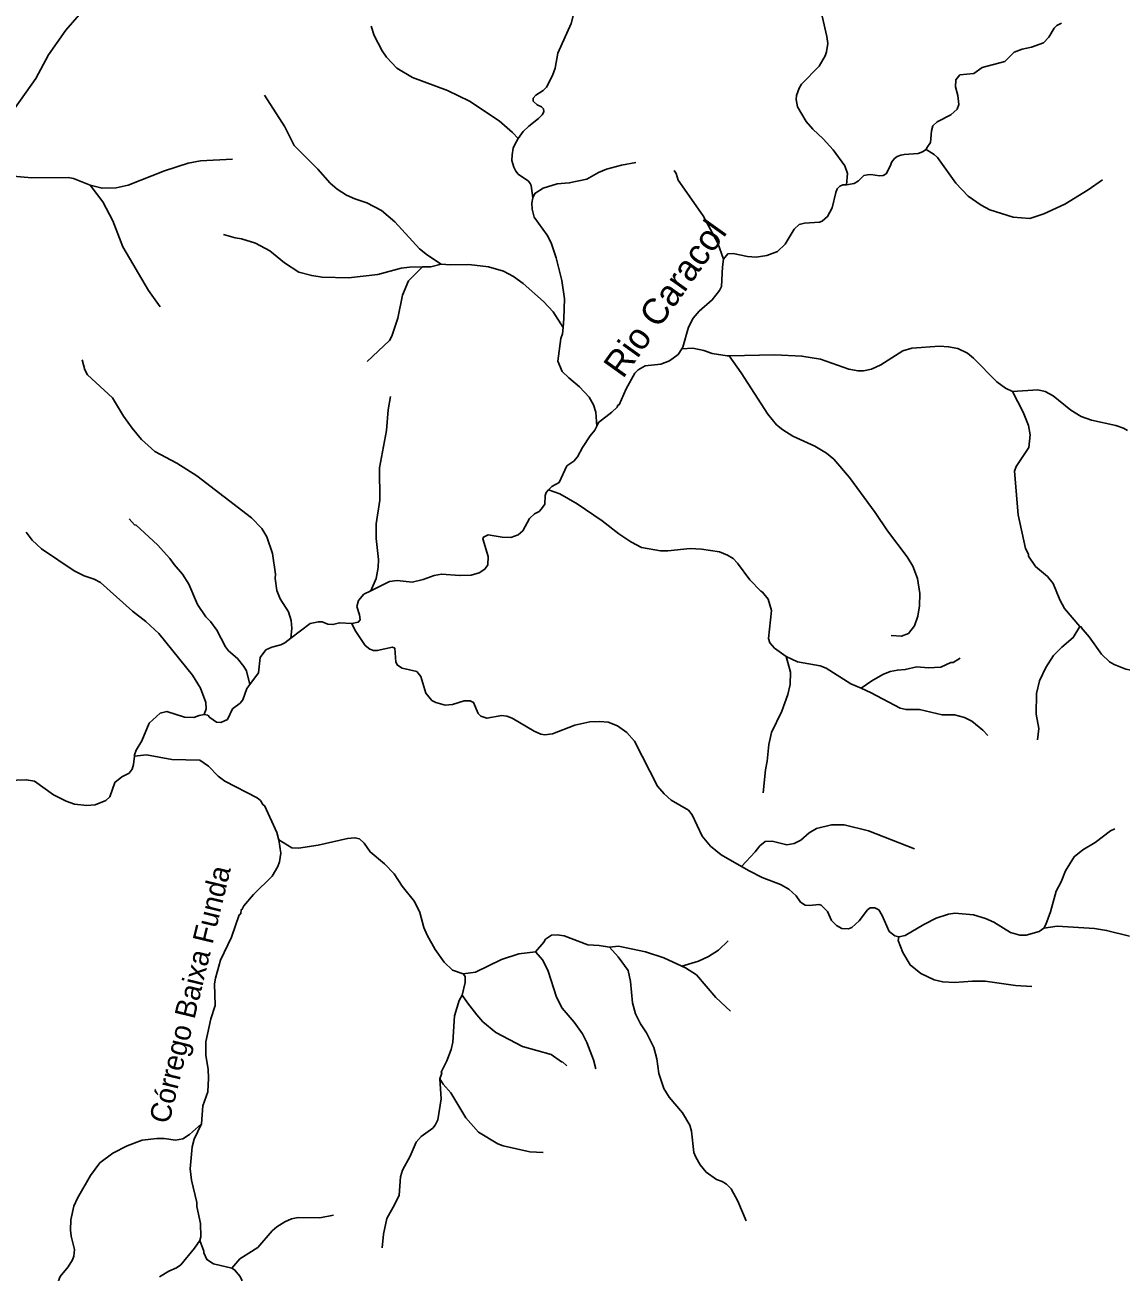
# Model space of a CAD drawing. Extents: x 280.4 to 335.6, y 8893.9 to 8949.5.
# Drawn here: x 321.4 to 329.87, y 8900.11 to 8909.74 of the extents above; entities that cross this region are included whole.
import ezdxf
from ezdxf.enums import TextEntityAlignment as Align

# ---------------------------------------------------------------- set-up
doc = ezdxf.new("R2010")
doc.units = 0
doc.header["$LTSCALE"] = 0.064
doc.layers.add('61', color=7, linetype='Continuous')
doc.layers.add('7', color=7, linetype='Continuous', lineweight=25)

msp = doc.modelspace()

# ---------------------------------------------------------------- linework, layer by layer
at = {"layer": '7'}
for points in [[(325.6886, 8910.0258), (325.6906, 8910.0157), (325.623, 8909.7531), (325.5192, 8909.5228), (325.4982, 8909.4077), (325.479, 8909.3501), (325.4308, 8909.2615), (325.4059, 8909.2345), (325.3501, 8909.1984), (325.3291, 8909.1772), (325.3294, 8909.1518), (325.3605, 8909.1249), (325.3924, 8909.1084), (325.4093, 8909.0931), (325.4101, 8909.0711), (325.3994, 8909.0462), (325.3707, 8909.0181), (325.2946, 8908.9593), (325.2526, 8908.9187), (325.2118, 8908.8645)], [(321.8219, 8909.8184), (321.7176, 8909.7002), (321.5856, 8909.5113), (321.4877, 8909.3291), (321.3251, 8909.0992), (321.3092, 8909.0653), (321.2855, 8908.9827), (321.2779, 8908.9278), (321.2778, 8908.7808), (321.2699, 8908.7207), (321.241, 8908.6561), (321.1893, 8908.5767)], [(327.5613, 8909.8081), (327.5978, 8909.6523), (327.6041, 8909.5974), (327.5963, 8909.5349), (327.5855, 8909.5042), (327.5373, 8909.4221), (327.4015, 8909.2829), (327.3839, 8909.2541), (327.3632, 8909.1965), (327.3615, 8909.167), (327.3714, 8909.1096), (327.4372, 8908.9964), (327.4897, 8908.9356), (327.5705, 8908.8611), (327.6476, 8908.7776), (327.7356, 8908.6528), (327.7564, 8908.5945), (327.7507, 8908.5076)], [(329.4108, 8909.7542), (329.3742, 8909.7378), (329.3533, 8909.7157), (329.3136, 8909.647), (329.2714, 8909.6033), (329.1788, 8909.5694), (329.1071, 8909.5546), (329.0454, 8909.5315), (328.9726, 8909.458), (328.7972, 8909.4141)], [(324.0776, 8909.7331), (324.1012, 8909.6593), (324.1614, 8909.5421), (324.197, 8909.4919), (324.2765, 8909.4077), (324.3977, 8909.3352), (324.6668, 8909.2358), (324.8361, 8909.1516), (325.0659, 8909.0001), (325.1696, 8908.9114), (325.2118, 8908.8645)], [(328.7972, 8909.4141), (328.7328, 8909.3662), (328.6252, 8909.3552), (328.5941, 8909.3187), (328.5929, 8909.2645), (328.6105, 8909.1958), (328.6166, 8909.1279), (328.6057, 8909.0918), (328.555, 8909.0467), (328.4505, 8908.9927), (328.4178, 8908.9623), (328.4073, 8908.9239), (328.3974, 8908.8335), (328.3703, 8908.7914), (328.3657, 8908.7804)], [(323.2542, 8909.2004), (323.4104, 8908.9547), (323.4819, 8908.8093), (323.6659, 8908.6284), (323.7609, 8908.519), (323.8144, 8908.4732), (323.8879, 8908.4282), (323.9519, 8908.3986), (324.0445, 8908.3669), (324.1574, 8908.3092), (324.2614, 8908.2217), (324.451, 8908.0128), (324.513, 8907.9626), (324.6186, 8907.8951)], [(325.2118, 8908.8645), (325.1849, 8908.8129), (325.1737, 8908.791), (325.1661, 8908.7378), (325.1644, 8908.6935), (325.1804, 8908.6426), (325.1954, 8908.6124), (325.2142, 8908.5902), (325.2925, 8908.535), (325.3056, 8908.5162), (325.314, 8908.5021), (325.327, 8908.407)], [(323.0068, 8908.7049), (322.7594, 8908.6913), (322.6629, 8908.6752), (322.4799, 8908.6148), (322.1995, 8908.5037), (322.1067, 8908.4833), (321.9983, 8908.4807), (321.9075, 8908.503)], [(328.3657, 8908.7804), (328.3376, 8908.7606), (328.3045, 8908.7481), (328.1962, 8908.7407), (328.1689, 8908.7358), (328.1413, 8908.7259), (328.1194, 8908.7095), (328.0993, 8908.6832), (328.0872, 8908.6514), (328.0557, 8908.5928), (328.032, 8908.5797), (328.0036, 8908.5762), (327.9383, 8908.5857), (327.9126, 8908.585), (327.8841, 8908.5779), (327.8643, 8908.5604), (327.8429, 8908.5383), (327.8098, 8908.5174), (327.7507, 8908.5076)], [(329.7281, 8908.546), (329.6176, 8908.4681), (329.4351, 8908.3574), (329.2747, 8908.2836), (329.1663, 8908.2467), (329.0375, 8908.2568), (328.8568, 8908.3138), (328.789, 8908.3493), (328.6884, 8908.4197), (328.5934, 8908.5194), (328.4521, 8908.7167), (328.4257, 8908.7411), (328.3657, 8908.7804)], [(326.1213, 8908.6782), (326.0105, 8908.6581), (325.8959, 8908.6285), (325.8325, 8908.6016), (325.7439, 8908.5503), (325.6081, 8908.5217), (325.5132, 8908.5152), (325.4065, 8908.4806), (325.3423, 8908.4403), (325.327, 8908.407)], [(326.4171, 8908.6176), (326.4335, 8908.5948), (326.4503, 8908.5435), (326.6424, 8908.2672), (326.755, 8908.0554), (326.8003, 8907.9338)], [(321.9075, 8908.503), (321.7777, 8908.5563), (321.7377, 8908.5632), (321.4569, 8908.5601), (321.281, 8908.576), (321.1893, 8908.5767)], [(322.4461, 8907.5652), (322.3561, 8907.6906), (322.1579, 8908.0285), (322.0809, 8908.2299), (322.0055, 8908.3745), (321.9075, 8908.503)], [(327.7507, 8908.5076), (327.7216, 8908.5067), (327.6984, 8908.4959), (327.6767, 8908.4758), (327.6665, 8908.4485), (327.6401, 8908.3281), (327.6039, 8908.2622), (327.5621, 8908.2273), (327.5412, 8908.2197), (327.4261, 8908.2098), (327.3843, 8908.1992), (327.3462, 8908.1637), (327.2766, 8908.0484), (327.216, 8907.9932), (327.1336, 8907.9602), (327.0523, 8907.9477), (326.986, 8907.953), (326.8745, 8907.9763), (326.8324, 8907.9734), (326.8003, 8907.9338)], [(325.327, 8908.407), (325.3178, 8908.3643), (325.3208, 8908.3197), (325.3362, 8908.2564), (325.4359, 8908.1179), (325.4678, 8908.0579), (325.506, 8907.9434), (325.5514, 8907.7684), (325.5702, 8907.6261), (325.567, 8907.4757), (325.5595, 8907.4055)], [(322.9365, 8908.1242), (323.0256, 8908.0969), (323.0759, 8908.0904), (323.1841, 8908.0562), (323.2955, 8907.9959), (323.4083, 8907.9037), (323.5194, 8907.8336), (323.6181, 8907.8056), (323.6986, 8907.7929), (323.9031, 8907.7893), (324.1284, 8907.815), (324.3093, 8907.8631), (324.3726, 8907.8706), (324.4728, 8907.873)], [(326.8003, 8907.9338), (326.7921, 8907.8723), (326.7837, 8907.7214), (326.7696, 8907.6901), (326.7121, 8907.6181), (326.6119, 8907.5306), (326.5646, 8907.4766), (326.5283, 8907.4086), (326.4853, 8907.2544), (326.4766, 8907.2408)], [(324.0474, 8907.1415), (324.2179, 8907.3043), (324.2372, 8907.3369), (324.2846, 8907.4764), (324.3199, 8907.6555), (324.3659, 8907.7661), (324.4728, 8907.873)], [(324.4728, 8907.873), (324.5382, 8907.8746), (324.6186, 8907.8951)], [(324.6186, 8907.8951), (324.69, 8907.8885), (324.8331, 8907.8914), (324.9832, 8907.8742), (325.0993, 8907.839), (325.1762, 8907.7992), (325.2522, 8907.744), (325.4093, 8907.6064), (325.4843, 8907.5263), (325.5595, 8907.4055)], [(325.5595, 8907.4055), (325.5543, 8907.3568), (325.5416, 8907.3197), (325.5194, 8907.1451)], [(326.8429, 8907.1859), (326.8265, 8907.1855), (326.7112, 8907.2036), (326.6481, 8907.2262), (326.5633, 8907.2451), (326.4766, 8907.2408)], [(329.0309, 8906.911), (328.9785, 8906.9368), (328.91, 8906.9855), (328.7318, 8907.1673), (328.6833, 8907.2074), (328.6088, 8907.2422), (328.5384, 8907.2566), (328.4674, 8907.2614), (328.254, 8907.2449), (328.1851, 8907.2254), (328.0139, 8907.116), (327.9435, 8907.084), (327.8808, 8907.0705), (327.8388, 8907.0696), (327.7669, 8907.0842), (327.5476, 8907.1605), (327.4055, 8907.1847), (327.1959, 8907.1942), (326.8429, 8907.1859)], [(321.8446, 8907.1551), (321.866, 8907.0786), (321.8847, 8907.0402), (322.078, 8906.8628), (322.1651, 8906.7216), (322.2319, 8906.6268), (322.3035, 8906.5412), (322.4065, 8906.4468), (322.577, 8906.3566), (322.7315, 8906.2587), (323.1526, 8905.9349), (323.2316, 8905.8527), (323.2718, 8905.7876), (323.3152, 8905.659), (323.3375, 8905.4998), (323.3346, 8905.4663), (323.3475, 8905.3736), (323.3732, 8905.3097), (323.4376, 8905.2096), (323.4593, 8905.1433), (323.4656, 8905.08), (323.4567, 8905.0053)], [(326.4766, 8907.2408), (326.4487, 8907.1971), (326.3815, 8907.1467), (326.3148, 8907.1207), (326.193, 8907.1096), (326.1411, 8907.0785), (326.1144, 8907.0535), (326.0467, 8906.9318), (325.9926, 8906.8068), (325.9828, 8906.8048), (325.9774, 8906.7909), (325.9374, 8906.7508), (325.8348, 8906.6726), (325.8209, 8906.6432)], [(328.0943, 8905.0261), (328.1747, 8905.0223), (328.2282, 8905.0419), (328.2758, 8905.1018), (328.301, 8905.177), (328.3145, 8905.2566), (328.3161, 8905.3512), (328.297, 8905.4664), (328.2615, 8905.5621), (328.2174, 8905.6343), (328.0667, 8905.835), (327.9723, 8905.9773), (327.7736, 8906.2465), (327.6513, 8906.3877), (327.5951, 8906.435), (327.5051, 8906.4884), (327.3349, 8906.5654), (327.257, 8906.6151), (327.2089, 8906.6544), (327.1408, 8906.737), (326.9348, 8907.0561), (326.8429, 8907.1859)], [(325.5194, 8907.1451), (325.5525, 8907.0662), (325.6035, 8907.0156), (325.6869, 8906.948), (325.7614, 8906.8666), (325.7938, 8906.8079), (325.8128, 8906.7513), (325.8209, 8906.6432)], [(324.2279, 8906.8725), (324.209, 8906.7699), (324.196, 8906.61), (324.1406, 8906.3218), (324.1437, 8906.0716), (324.1149, 8905.8891), (324.1165, 8905.7749), (324.1341, 8905.6142), (324.1308, 8905.5519), (324.1167, 8905.4677), (324.0736, 8905.3718)], [(329.9197, 8906.6108), (329.8897, 8906.6281), (329.8306, 8906.649), (329.6414, 8906.6906), (329.5613, 8906.7182), (329.4821, 8906.7657), (329.3467, 8906.8772), (329.2853, 8906.9111), (329.2286, 8906.9224), (329.0309, 8906.911)], [(329.5529, 8905.0957), (329.433, 8905.2362), (329.3982, 8905.3023), (329.3472, 8905.4293), (329.3028, 8905.4814), (329.2086, 8905.5599), (329.1563, 8905.6392), (329.1549, 8905.6543), (329.1335, 8905.699), (329.0759, 8905.9596), (329.0473, 8906.2954), (329.0599, 8906.3307), (329.1591, 8906.4795), (329.1685, 8906.5762), (329.1554, 8906.648), (329.1134, 8906.7513), (329.0309, 8906.911)], [(325.8209, 8906.6432), (325.8059, 8906.6113), (325.7682, 8906.5686), (325.7094, 8906.4794), (325.6705, 8906.4069), (325.643, 8906.3737), (325.5892, 8906.3363), (325.5308, 8906.2087), (325.4724, 8906.1777), (325.4472, 8906.1504)], [(325.4472, 8906.1504), (325.4302, 8906.132), (325.4218, 8906.1084), (325.4185, 8906.0411), (325.3944, 8906.0037), (325.3745, 8905.9852), (325.3387, 8905.9666), (325.2996, 8905.9308), (325.2487, 8905.8354), (325.2125, 8905.8034), (325.1576, 8905.7839), (325.0906, 8905.7847), (324.9812, 8905.803), (324.944, 8905.7856), (324.9404, 8905.7742), (324.9817, 8905.6359), (324.9799, 8905.5728), (324.9553, 8905.5392), (324.9119, 8905.5109), (324.851, 8905.4923), (324.7658, 8905.4895), (324.7631, 8905.4897), (324.6219, 8905.4989), (324.5632, 8905.4903), (324.4779, 8905.4586), (324.3948, 8905.4387), (324.2788, 8905.4511), (324.2197, 8905.4444), (324.0736, 8905.3718)], [(327.2842, 8904.8644), (327.2838, 8904.8646), (327.1934, 8904.9285), (327.1569, 8904.9704), (327.1474, 8905.0032), (327.1695, 8905.2203), (327.1434, 8905.3077), (327.1016, 8905.362), (327.087, 8905.368), (327.0021, 8905.4554), (326.9083, 8905.586), (326.8752, 8905.6205), (326.831, 8905.6475), (326.7686, 8905.6727), (326.6305, 8905.694), (326.5419, 8905.6973), (326.3705, 8905.6814), (326.3116, 8905.6814), (326.1668, 8905.706), (326.0835, 8905.7493), (325.9907, 8905.8116), (325.8629, 8905.9132), (325.6685, 8906.044), (325.5357, 8906.1208), (325.4472, 8906.1504)], [(322.2083, 8905.9284), (322.25, 8905.8822), (322.2627, 8905.878), (322.4261, 8905.7277), (322.5227, 8905.6201), (322.5545, 8905.5737), (322.6185, 8905.4998), (322.6683, 8905.424), (322.7368, 8905.2649), (322.7994, 8905.171), (322.836, 8905.1338), (322.8852, 8905.0677), (322.9516, 8904.938), (322.975, 8904.9085), (323.0434, 8904.8497), (323.0938, 8904.7876), (323.113, 8904.7542), (323.1395, 8904.6481)], [(321.411, 8905.8237), (321.4594, 8905.7623), (321.5316, 8905.6947), (321.7833, 8905.5248), (321.859, 8905.4876), (321.9367, 8905.4622), (321.9853, 8905.4347), (322.2339, 8905.2136), (322.3376, 8905.1349), (322.4357, 8905.0432), (322.697, 8904.7198), (322.7583, 8904.62), (322.8007, 8904.5081), (322.8035, 8904.4603), (322.7877, 8904.4163)], [(324.0736, 8905.3718), (324.0213, 8905.3458), (323.9786, 8905.2957), (323.9678, 8905.2501)], [(323.9678, 8905.2501), (323.987, 8905.1849), (323.9915, 8905.1474), (323.9774, 8905.129), (323.9292, 8905.1194)], [(323.9292, 8905.1194), (323.8316, 8905.1247), (323.7822, 8905.1106), (323.7438, 8905.1139), (323.6975, 8905.1308), (323.6699, 8905.1327), (323.607, 8905.1185), (323.4567, 8905.0053)], [(326.9386, 8903.2424), (326.7824, 8903.3322), (326.6983, 8903.4004), (326.6358, 8903.4773), (326.5568, 8903.6407), (326.5289, 8903.6768), (326.3962, 8903.7546), (326.3421, 8903.8028), (326.2895, 8903.8632), (326.1118, 8904.2118), (326.0522, 8904.2767), (325.9795, 8904.329), (325.9076, 8904.3574), (325.8451, 8904.3621), (325.766, 8904.3589), (325.6509, 8904.335), (325.4774, 8904.2661), (325.4184, 8904.2599), (325.3884, 8904.2654), (325.3376, 8904.2872), (325.1656, 8904.3891), (325.1263, 8904.4048), (325.0874, 8904.4089), (324.9711, 8904.3875), (324.9258, 8904.4035), (324.9045, 8904.4239), (324.8682, 8904.51), (324.8423, 8904.5217), (324.7956, 8904.5232), (324.7065, 8904.4934), (324.65, 8904.4886), (324.5781, 8904.5079), (324.5457, 8904.5246), (324.4993, 8904.5805), (324.4602, 8904.7088), (324.4291, 8904.749), (324.3159, 8904.7737), (324.28, 8904.7973), (324.2681, 8904.8202), (324.2612, 8904.9283), (324.2426, 8904.9376), (324.1245, 8904.9106), (324.1015, 8904.9108), (324.0959, 8904.9108), (324.0671, 8904.9204), (324.0298, 8904.9495), (323.9535, 8905.0642), (323.9292, 8905.1194)], [(329.2251, 8904.2212), (329.2343, 8904.3085), (329.2147, 8904.4203), (329.2173, 8904.5784), (329.2419, 8904.6764), (329.289, 8904.7799), (329.3499, 8904.8726), (329.4128, 8904.9355), (329.502, 8905.0105), (329.5529, 8905.0957)], [(330.357, 8904.701), (330.308, 8904.7102), (330.105, 8904.7251), (329.9068, 8904.7653), (329.8172, 8904.8021), (329.7809, 8904.8239), (329.7188, 8904.8834), (329.6255, 8905.0151), (329.5628, 8905.0876), (329.5645, 8905.0926), (329.5529, 8905.0957)], [(323.4567, 8905.0053), (323.4092, 8904.9695), (323.3792, 8904.955), (323.309, 8904.9376), (323.2638, 8904.9147), (323.2195, 8904.8576), (323.206, 8904.7373), (323.1395, 8904.6481)], [(327.1059, 8903.8127), (327.1233, 8903.9889), (327.1375, 8904.0572), (327.1505, 8904.1844), (327.1699, 8904.2777), (327.2492, 8904.4414), (327.2971, 8904.5699), (327.3148, 8904.6475), (327.3166, 8904.7435), (327.2842, 8904.8644)], [(327.8625, 8904.6193), (327.7841, 8904.6545), (327.5933, 8904.7746), (327.5462, 8904.7923), (327.3711, 8904.8243), (327.2842, 8904.8644)], [(328.6277, 8904.851), (328.5742, 8904.8191), (328.5552, 8904.8179), (328.4777, 8904.7812), (328.3794, 8904.778), (328.2941, 8904.7858), (328.2033, 8904.7636), (328.1435, 8904.7599), (328.0875, 8904.7474), (328.0314, 8904.7241), (327.9461, 8904.6769), (327.8625, 8904.6193)], [(323.1395, 8904.6481), (323.1164, 8904.6172), (323.0861, 8904.5294), (323.0657, 8904.5045), (323.0057, 8904.4599), (322.9663, 8904.3768), (322.9169, 8904.3543), (322.883, 8904.3571), (322.8309, 8904.3924), (322.8147, 8904.4117), (322.7877, 8904.4163)], [(328.8424, 8904.2537), (328.8039, 8904.2959), (328.7182, 8904.3647), (328.6614, 8904.3934), (328.5832, 8904.4131), (328.4874, 8904.4132), (328.3145, 8904.4547), (328.2098, 8904.4548), (328.1653, 8904.4642), (327.941, 8904.584), (327.8625, 8904.6193)], [(322.7877, 8904.4163), (322.7487, 8904.4092), (322.7075, 8904.3925), (322.6365, 8904.3958), (322.4981, 8904.4384), (322.4463, 8904.4255), (322.3613, 8904.3503), (322.306, 8904.2133), (322.2611, 8904.1422), (322.2489, 8904.1059), (322.248, 8904.0952)], [(322.248, 8904.0952), (322.2422, 8904.0296), (322.2315, 8903.9944), (322.2077, 8903.9631), (322.1504, 8903.9362), (322.0973, 8903.8919), (322.0576, 8903.7812), (322.0285, 8903.7533), (321.9447, 8903.7195), (321.8799, 8903.7144), (321.7848, 8903.7251), (321.7199, 8903.746), (321.6239, 8903.7971), (321.4759, 8903.9012), (321.4121, 8903.9126), (321.269, 8903.9062)], [(323.3635, 8903.4493), (323.3616, 8903.456), (323.3477, 8903.5061), (323.2569, 8903.7086), (323.2409, 8903.7205), (323.2231, 8903.7514), (323.1965, 8903.7726), (322.9458, 8903.9005), (322.8964, 8903.9396), (322.821, 8904.0165), (322.753, 8904.0629), (322.538, 8904.069), (322.3422, 8904.1045), (322.248, 8904.0952)], [(328.2747, 8903.378), (327.92, 8903.5179), (327.7306, 8903.5637), (327.634, 8903.5639), (327.517, 8903.5362), (327.4622, 8903.5032), (327.3974, 8903.4456), (327.3447, 8903.4199), (327.2878, 8903.4106), (327.1743, 8903.4389), (327.1207, 8903.4354), (327.0802, 8903.4027), (327.0436, 8903.3548), (326.9386, 8903.2424)], [(329.8219, 8903.5332), (329.7896, 8903.5192), (329.6695, 8903.4288), (329.5743, 8903.3716), (329.5084, 8903.3178), (329.4422, 8903.2094), (329.4084, 8903.1241), (329.3704, 8903.0513), (329.3268, 8902.8922), (329.2899, 8902.7947), (329.2736, 8902.7667)], [(322.7678, 8901.2545), (322.778, 8901.3953), (322.8147, 8901.5017), (322.8211, 8901.6072), (322.8178, 8901.6776), (322.8004, 8901.7824), (322.8004, 8901.8879), (322.8376, 8902.0655), (322.8722, 8902.1695), (322.8675, 8902.3377), (322.8739, 8902.3805), (322.9143, 8902.5183), (322.9989, 8902.6978), (323.0576, 8902.8682), (323.0705, 8902.8772), (323.0742, 8902.9093), (323.082, 8902.9122), (323.0944, 8902.9379), (323.1694, 8903.0264), (323.3137, 8903.1693), (323.3571, 8903.2416), (323.3702, 8903.2791), (323.3791, 8903.3457), (323.3635, 8903.4493)], [(324.7886, 8902.4129), (324.7051, 8902.4429), (324.6422, 8902.5043), (324.573, 8902.6021), (324.5103, 8902.7125), (324.4844, 8902.7707), (324.4529, 8902.8885), (324.4129, 8902.9736), (324.3166, 8903.0897), (324.2551, 8903.1871), (324.1809, 8903.263), (324.0691, 8903.3554), (324.0241, 8903.4225), (323.988, 8903.456), (323.9518, 8903.4648), (323.895, 8903.4601), (323.6667, 8903.4062), (323.5153, 8903.3834), (323.4651, 8903.3875), (323.3635, 8903.4493)], [(328.1527, 8902.6997), (328.1236, 8902.7078), (328.0786, 8902.7416), (328.0251, 8902.8635), (327.9984, 8902.907), (327.9683, 8902.9241), (327.9329, 8902.9242), (327.9111, 8902.9076), (327.848, 8902.8225), (327.7915, 8902.7719), (327.7644, 8902.7613), (327.7133, 8902.7645), (327.6732, 8902.7876), (327.6339, 8902.8265), (327.6028, 8902.8953), (327.5542, 8902.9435), (327.5356, 8902.9483), (327.4637, 8902.9403), (327.4314, 8902.9439), (327.3953, 8902.9679), (327.3597, 8903.0154), (327.3039, 8903.0675), (327.2389, 8903.1046), (327.0985, 8903.158), (326.9984, 8903.208), (326.9386, 8903.2424)], [(329.2736, 8902.7667), (329.2378, 8902.7416), (329.1384, 8902.7136), (329.0894, 8902.7132), (329.0176, 8902.7328), (328.8871, 8902.8123), (328.8228, 8902.8423), (328.7303, 8902.8698), (328.5864, 8902.8825), (328.5384, 8902.8746), (328.4433, 8902.843), (328.3465, 8902.7947), (328.2019, 8902.7098), (328.1527, 8902.6997)], [(325.9187, 8902.6209), (325.8382, 8902.6332), (325.7518, 8902.6367), (325.5695, 8902.7068), (325.5133, 8902.7162), (325.4711, 8902.7114), (325.4234, 8902.6808), (325.4113, 8902.658), (325.348, 8902.584)], [(329.9367, 8902.7037), (329.7587, 8902.7486), (329.6643, 8902.7627), (329.3764, 8902.7819), (329.2736, 8902.7667)], [(325.9187, 8902.6209), (325.9877, 8902.6265), (326.1964, 8902.5838), (326.3395, 8902.5382), (326.4765, 8902.4728)], [(326.9751, 8900.5061), (326.9101, 8900.6571), (326.8591, 8900.7524), (326.8218, 8900.7896), (326.7882, 8900.8103), (326.7453, 8900.8257), (326.6663, 8900.8814), (326.6201, 8900.9376), (326.585, 8900.9969), (326.5713, 8901.0332), (326.5525, 8901.1978), (326.5391, 8901.2456), (326.4834, 8901.341), (326.3785, 8901.4623), (326.3396, 8901.5293), (326.2998, 8901.6442), (326.2851, 8901.7568), (326.2613, 8901.8456), (326.2051, 8901.9583), (326.1588, 8902.0287), (326.1206, 8902.1059), (326.0966, 8902.1911), (326.0817, 8902.3542), (326.0617, 8902.4398), (325.9851, 8902.5448), (325.9187, 8902.6209)], [(326.8362, 8902.6688), (326.7613, 8902.5973), (326.6833, 8902.5469), (326.6053, 8902.5129), (326.4765, 8902.4728)], [(329.1802, 8902.3157), (329.0542, 8902.3248), (328.8199, 8902.3565), (328.7231, 8902.3581), (328.5848, 8902.347), (328.4934, 8902.3514), (328.4258, 8902.3664), (328.3249, 8902.4157), (328.2424, 8902.4832), (328.1853, 8902.5782), (328.1485, 8902.6716), (328.1527, 8902.6997)], [(325.348, 8902.584), (325.2175, 8902.5677), (325.0847, 8902.5247), (324.8841, 8902.4275), (324.7886, 8902.4129)], [(325.8133, 8901.679), (325.7957, 8901.75), (325.7434, 8901.8833), (325.71, 8901.9506), (325.6454, 8902.0414), (325.5518, 8902.1485), (325.5092, 8902.234), (325.4452, 8902.4356), (325.4043, 8902.5206), (325.348, 8902.584)], [(326.4765, 8902.4728), (326.505, 8902.4592), (326.59, 8902.4049), (326.741, 8902.2302), (326.8529, 8902.1263)], [(324.7799, 8902.2496), (324.8041, 8902.3478), (324.8025, 8902.3942), (324.7886, 8902.4129)], [(324.609, 8901.6019), (324.6227, 8901.6479), (324.6176, 8901.6543), (324.6618, 8901.7408), (324.6942, 8901.8287), (324.7083, 8901.8863), (324.72, 8902.089), (324.756, 8902.2068), (324.7799, 8902.2496)], [(325.5889, 8901.7029), (325.5577, 8901.7307), (325.5467, 8901.7331), (325.467, 8901.7903), (325.2453, 8901.8539), (325.0404, 8901.9608), (324.9409, 8902.044), (324.893, 8902.0964), (324.8226, 8902.191), (324.7799, 8902.2496)], [(324.1617, 8900.2973), (324.1727, 8900.4034), (324.1983, 8900.5246), (324.2613, 8900.6346), (324.2938, 8900.7048), (324.3038, 8900.8452), (324.3183, 8900.8969), (324.3781, 8901.0055), (324.4257, 8901.1144), (324.4644, 8901.1572), (324.5526, 8901.2221), (324.5717, 8901.2445), (324.5916, 8901.2858), (324.6169, 8901.4482), (324.609, 8901.6019)], [(325.4049, 8901.0348), (325.3024, 8901.0399), (325.0962, 8901.0854), (325.0563, 8901.1009), (324.9078, 8901.1914), (324.8084, 8901.3014), (324.6938, 8901.4945), (324.6342, 8901.5609), (324.609, 8901.6019)], [(321.6619, 8900.0433), (321.674, 8900.0773), (321.7363, 8900.1522), (321.7703, 8900.2056), (321.7803, 8900.2327), (321.7861, 8900.2838), (321.7603, 8900.3872), (321.7545, 8900.4343), (321.7579, 8900.5141), (321.7802, 8900.6208), (321.8076, 8900.6827), (321.9079, 8900.8554), (321.9811, 8900.9533), (322.0807, 8901.0291), (322.1933, 8901.0854), (322.307, 8901.1281), (322.4213, 8901.1426), (322.4788, 8901.1411), (322.5653, 8901.1285), (322.623, 8901.1405), (322.6739, 8901.1731), (322.7678, 8901.2545)], [(322.7543, 8900.3552), (322.7614, 8900.3817), (322.7586, 8900.4848), (322.7302, 8900.6175), (322.7296, 8900.6485), (322.6884, 8900.8197), (322.6788, 8900.9067), (322.6949, 8901.0787), (322.7111, 8901.1371), (322.7678, 8901.2545)], [(323.7865, 8900.5511), (323.6799, 8900.5302), (323.5136, 8900.5333), (323.4624, 8900.5221), (323.4106, 8900.4993), (323.3494, 8900.4602), (323.3137, 8900.4294), (323.2012, 8900.3013), (323.0632, 8900.2125), (323.0006, 8900.1406)], [(322.442, 8900.0727), (322.515, 8900.1188), (322.5746, 8900.144), (322.6063, 8900.1668), (322.7128, 8900.2952), (322.7543, 8900.3552)], [(323.0006, 8900.1406), (322.8596, 8900.1753), (322.8082, 8900.2075), (322.7833, 8900.2592), (322.7839, 8900.2715), (322.7543, 8900.3552)], [(323.4752, 8899.5326), (323.4321, 8899.5675), (323.3248, 8899.61), (323.286, 8899.6351), (323.2198, 8899.6984), (323.1912, 8899.7354), (323.1007, 8899.9088), (323.0851, 8899.952), (323.0788, 8900.048), (323.065, 8900.0753), (323.0219, 8900.1281), (323.0006, 8900.1406)]]:
    msp.add_lwpolyline(points, dxfattribs=at)

# ---------------------------------------------------------------- texts
at = {"layer": '61'}
for s, height, rotation, p in [('Rio Caracol', 0.2, 54.462, (326.428, 8907.5723)), ('Córrego Baixa Funda', 0.16, 76.399, (322.7549, 8902.2374))]:
    msp.add_text(s, height=height, rotation=rotation, dxfattribs=at).set_placement(p, align=Align.CENTER)

doc.saveas('drawing.dxf')
